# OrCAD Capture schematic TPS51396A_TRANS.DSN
size D; title: TPS51396A 4.5-V to 24-V, 8-A Synchronous Step-Down; rev: 1.0; note: Datasheet: SLVSEY3B                        EVM: NA; note: Synchronous Step Down Converter; note: Voltage Regulator
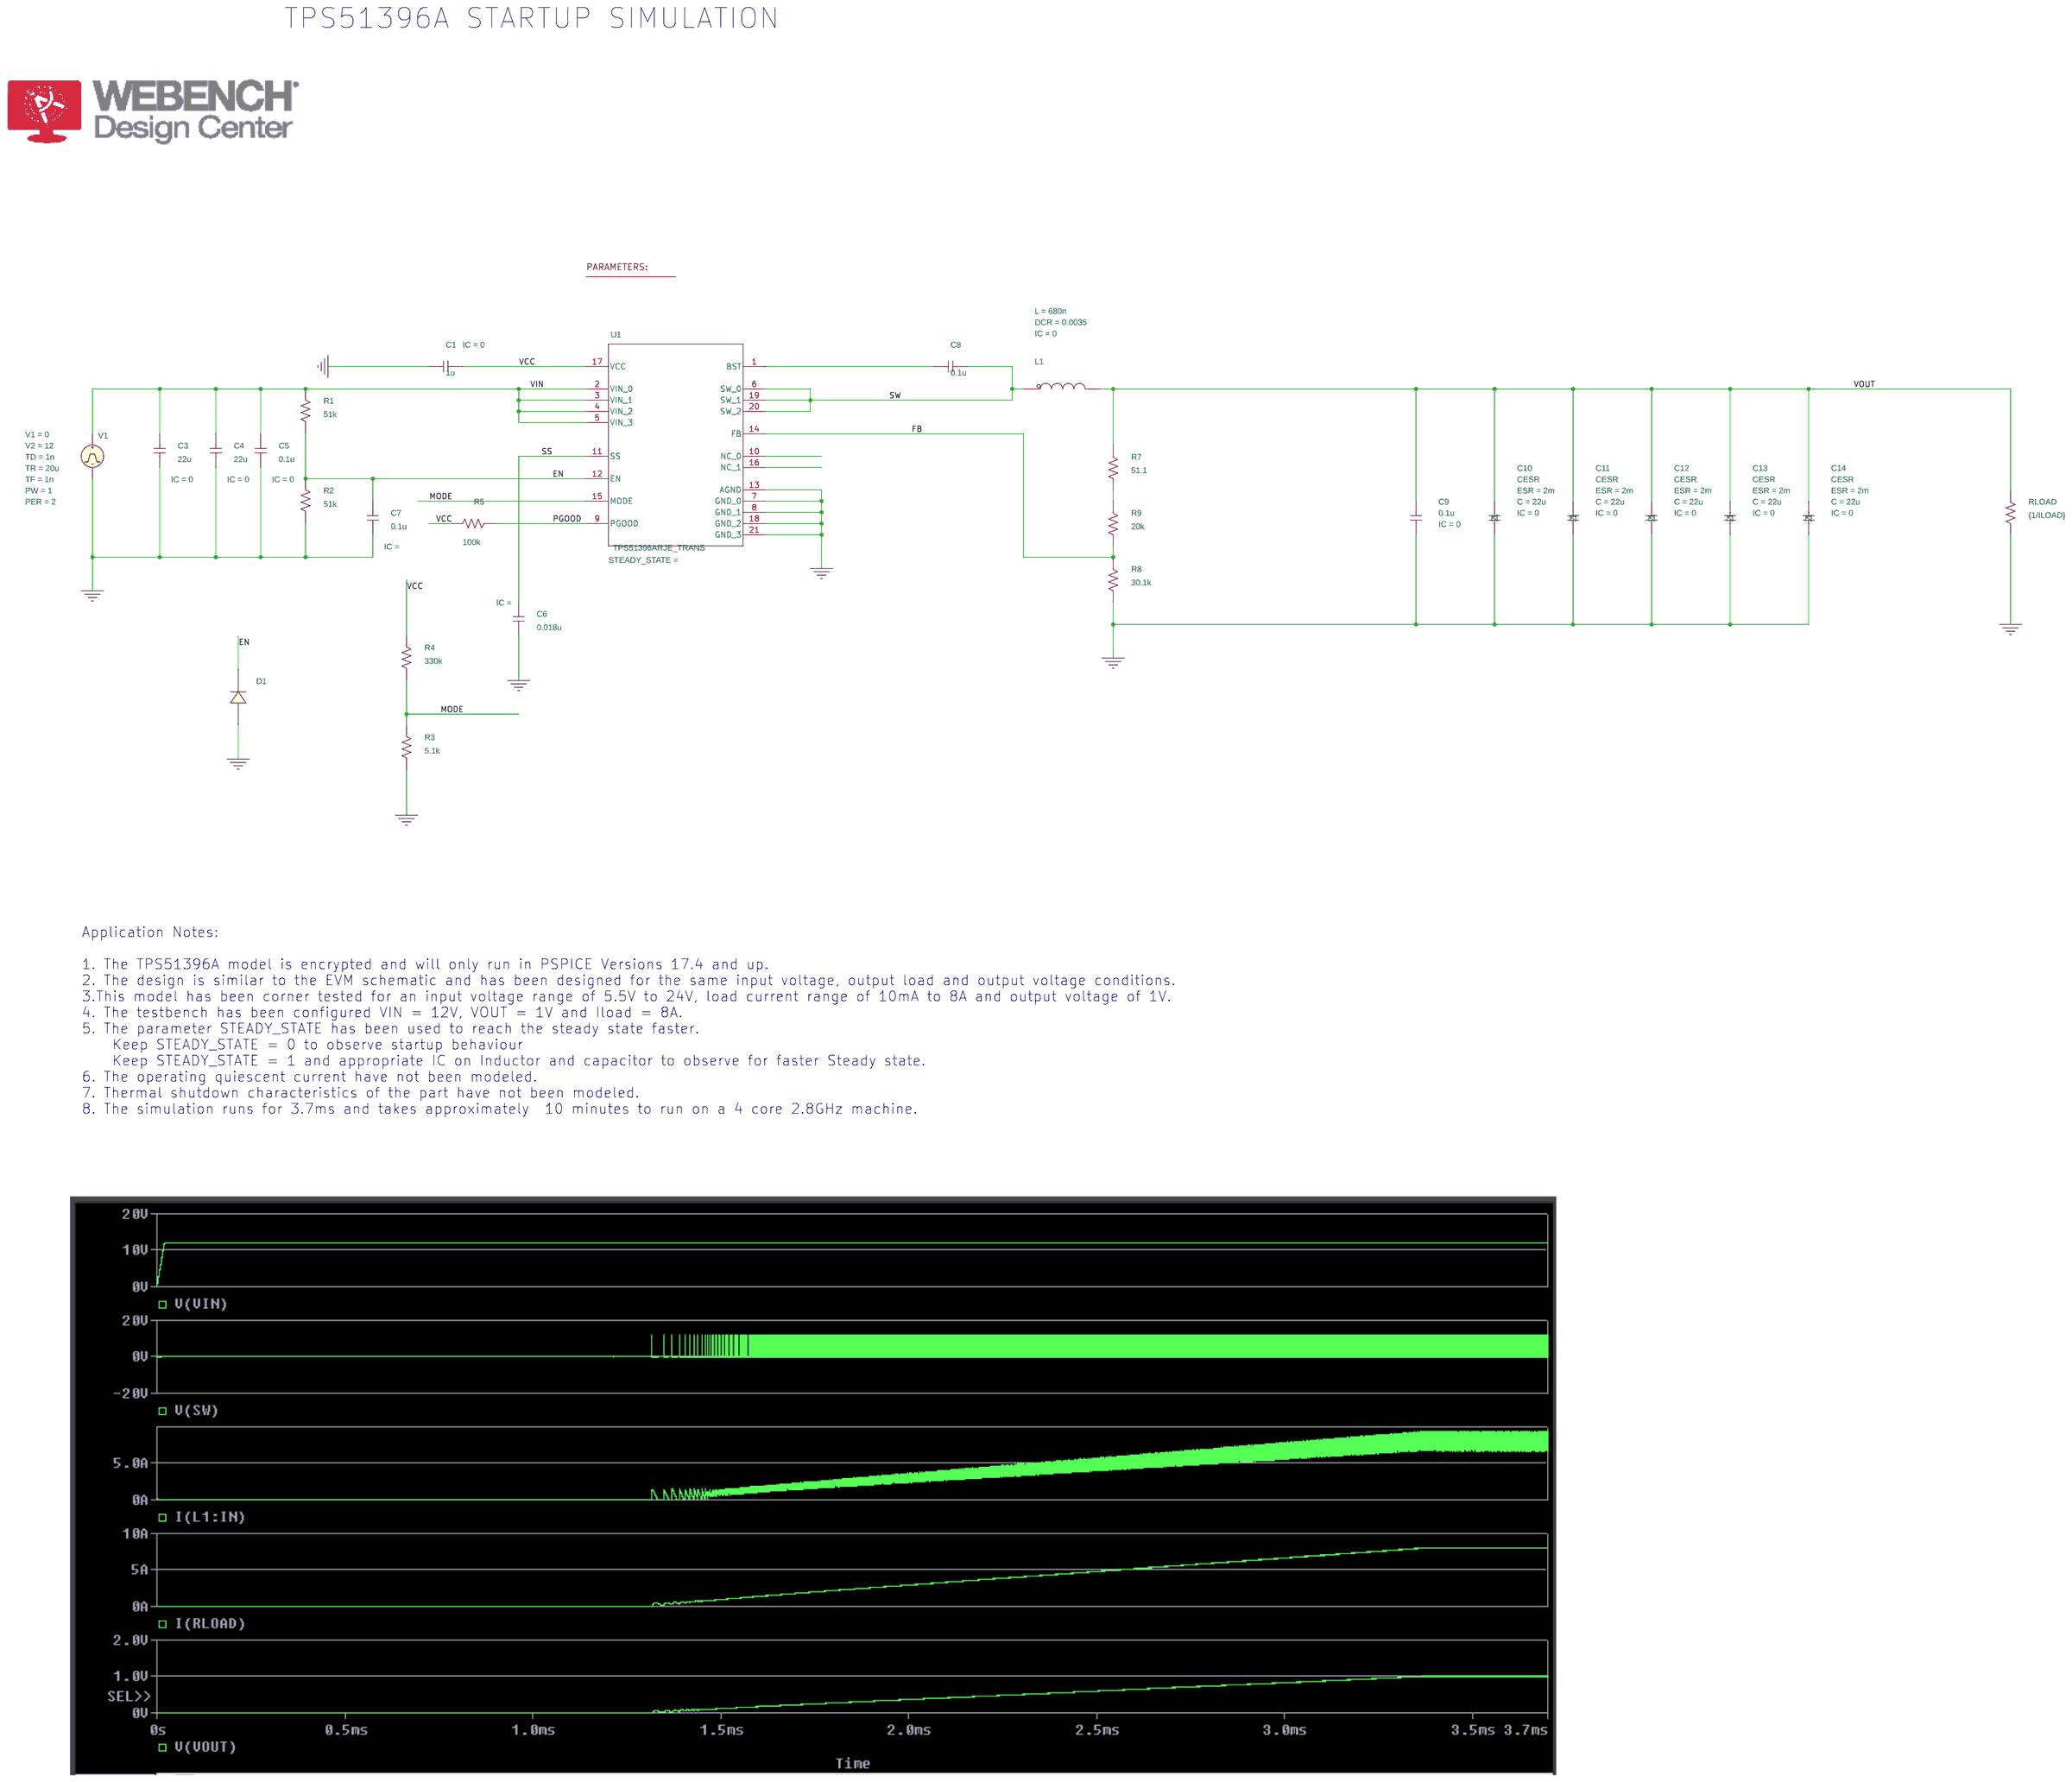
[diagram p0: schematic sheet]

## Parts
1  PARAM
C1  1u  [RAD/CK05]
C3  22u  [RAD/CK05]
C4  22u  [RAD/CK05]
C5  0.1u  [RAD/CK05]
C6  0.018u  [RAD/CK05]
C7  0.1u  [RAD/CK05]
C8  0.1u  [RAD/CK05]
C9  0.1u  [RAD/CK05]
C10  CESR
C11  CESR
C12  CESR
C13  CESR
C14  CESR
D1  D_D1
L1  LDCR
R1  51k  [AX/RC05]
R2  51k  [AX/RC05]
R3  5.1k  [AX/RC05]
R4  330k  [AX/RC05]
R5  100k  [AX/RC05]
R7  51.1  [AX/RC05]
R8  30.1k  [AX/RC05]
R9  20k  [AX/RC05]
RLOAD  {1/ILOAD}  [AX/RC05]
U1  TPS51396ARJE_TRANS  [RJE0020A-MFG]
V1  VPULSE

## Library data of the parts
1 = PARAM: ILOAD: 8
C1 C3-C5 C9 = C: IC: 0
C6-C8 = C
C10 = CESR_3: C: 22u; ESL: 0; ESR: 2m; IC: 0; PSpiceTemplate: X^@REFDES %1 %2 @MODEL PARAMS: ?C|C=@C||C=10U| ?ESR|ESR=@ESR||ESR=2M| ?IC|IC=@IC||IC=1N|; X: 1
C11 = CESR_1: C: 22u; ESL: 0; ESR: 2m; IC: 0; PSpiceTemplate: X^@REFDES %1 %2 @MODEL PARAMS: ?C|C=@C||C=10U| ?ESR|ESR=@ESR||ESR=2M| ?IC|IC=@IC||IC=1N|; X: 1
C12 = CESR_4: C: 22u; ESL: 0; ESR: 2m; IC: 0; PSpiceTemplate: X^@REFDES %1 %2 @MODEL PARAMS: ?C|C=@C||C=10U| ?ESR|ESR=@ESR||ESR=2M| ?IC|IC=@IC||IC=1N|; X: 1
C13 = CESR_2: C: 22u; ESL: 0; ESR: 2m; IC: 0; PSpiceTemplate: X^@REFDES %1 %2 @MODEL PARAMS: ?C|C=@C||C=10U| ?ESR|ESR=@ESR||ESR=2M| ?IC|IC=@IC||IC=1N|; X: 1
C14 = CESR: C: 22u; ESL: 0; ESR: 2m; IC: 0; PSpiceTemplate: X^@REFDES %1 %2 @MODEL PARAMS: ?C|C=@C||C=10U| ?ESR|ESR=@ESR||ESR=2M| ?IC|IC=@IC||IC=1N| ?; X: 1
D1 = D_D1: PSpiceTemplate: x^@REFDES %A %C @MODEL ?AREA/@AREA/
L1 = LDCR_0: DCR: 0.0035; IC: 0; L: 680n; PSpiceTemplate: X^@REFDES %IN %OUT @MODEL PARAMS:  ?L|L=@L||L=1u|  ?DCR|DCR=@DCR||DCR=0.01| ?IC|IC=@IC||IC=0|
R1-R5 R7-R9 RLOAD = R
U1 = TPS51396ARJE_TRANS
V1 = VPULSE: PER: 2; PW: 1; TD: 1n; TF: 1n; TR: 20u; V1: 0; V2: 12

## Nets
VCC: C1.2 R4.2 R5.2 U1.17(VCC)
VIN: C3.1 C4.1 C5.1 R1.2 U1.2(VIN_0) U1.3(VIN_1) U1.4(VIN_2) U1.5(VIN_3) V1.1(+)
0: C1.1 C3.2 C4.2 C5.2 C6.2 C7.2 C9.1 C10.2 C11.2 C12.2 C13.2 C14.2 D1.2(A) R2.1 R3.1 R8.2 RLOAD.2 U1.7(GND_0) U1.8(GND_1) U1.13(AGND) U1.18(GND_2) U1.21(GND_3) V1.2(-)
EN: C7.1 D1.1(C) R1.1 R2.2 U1.12(EN)
FB: R8.1 R9.2 U1.14(FB)
MODE: R3.2 R4.1 U1.15(MODE)
PGOOD: R5.1 U1.9(PGOOD)
SS: C6.1 U1.11(SS)
SW: C8.2 L1.1(IN) U1.6(SW_0) U1.19(SW_1) U1.20(SW_2)
VOUT: C9.2 C10.1 C11.1 C12.1 C13.1 C14.1 L1.3(OUT) R7.1 RLOAD.1
N16771022: R7.2 R9.1
N16773520: C8.1 U1.1(BST)

Not connected (* = marked no-connect by the designer): U1 10(NC_0) 16(NC_1)

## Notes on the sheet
- TPS51396A STARTUP SIMULATION
- Application Notes:
  1. The TPS51396A model is encrypted and will only run in PSPICE Versions 17.4 and up.
  2. The design is similar to the EVM schematic and has been designed for the same input voltage, output load and output voltage conditions.
  3.This model has been corner tested for an input voltage range of 5.5V to 24V, load current range of 10mA to 8A and output voltage of 1V.
  4. The testbench has been configured VIN = 12V, VOUT = 1V and Iload = 8A.
  5. The parameter STEADY_STATE has been used to reach the steady state faster.
      Keep STEADY_STATE = 0 to observe startup behaviour
      Keep STEADY_STATE = 1 and appropriate IC on Inductor and capacitor to observe for faster Steady state.
  6. The operating quiescent current have not been modeled.
  7. Thermal shutdown characteristics of the part have not been modeled.
  8. The simulation runs for 3.7ms and takes approximately  10 minutes to run on a 4 core 2.8GHz machine.
